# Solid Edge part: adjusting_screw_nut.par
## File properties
Title: Adjusting screw nut
Author: Deepak Maini
Template: Normal.par
Last saved by: Robert a Rhodes jr
Revision: 6
Application: Solid Edge
Material: aluminum
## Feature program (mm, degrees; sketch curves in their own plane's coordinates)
sketch for "unnamed RevolvedProtrusion 1" plane through (0, 0, 0) normal (0, -1, 0) x-axis (1, 0, 0)
  line (25.4, 9.7462) -> (74.676, 9.7462)
  line (76.2, 8.2222) -> (74.676, 9.7462)
  line (76.2, -26.8298) -> (76.2, 8.2222)
  line (76.2, -26.8298) -> (74.676, -28.3538)
  line (74.676, -28.3538) -> (47.625, -28.3538)
  line (47.625, -28.3538) -> (47.625, -60.1038)
  line (47.625, -60.1038) -> (25.4, -60.1038)
  line (25.4, -60.1038) -> (25.4, 9.7462)
revolve "unnamed RevolvedProtrusion 1" add full turn 360 deg
sketch for "unnamed Hole 1" plane through (76.2, 0, 0) normal (1, 0, 0) x-axis (0, 1, 0)
  hole centre (0, -9.3038) bore radius 9.5123
hole "unnamed Hole 1" finite
pattern "unnamed Pattern 1" of "unnamed Hole 1"
pattern "unnamed Pattern 2"
sketch for "unnamed Cutout 1" plane through (0, 0, 9.7462) normal (0, 0, 1) x-axis (1, 0, 0)
extrude "unnamed Cutout 1" cut through along -normal
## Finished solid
Body 1: solid body, 16 faces, 16 edges, 4 vertices.
  Faces by surface: cylinder 7, cone 6, plane 3
  Edges by curve: circle 12, intersection 4
Bounding box of the edges (mm): 152.400 x 152.400 x 69.850, from (-76.2, -76.2, -60.1038) to (76.2, 76.2, 9.7462).
Cylindrical faces by radius (mm): R9.5123 x4, R38.1 x1, R47.625 x1, R76.2 x1
Conical faces (half-angle, radius in mm at the cone's reference point): 45 deg R74.676 x1, 45 deg R76.2 x1, 59 deg R9.5123 x4
Planar faces by outward normal: +z 1, -z 2
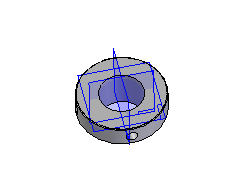
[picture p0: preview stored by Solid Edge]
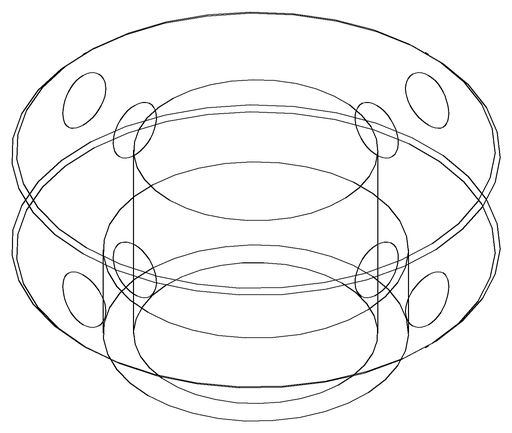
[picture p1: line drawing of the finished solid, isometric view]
